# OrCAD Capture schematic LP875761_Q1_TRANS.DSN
size Custom; title: LP875761-Q1 4-Phase 16A Buck Converter with Integrated Switches; rev: 1.0; note: SNVSxxxx –SEPTEMBER 2020
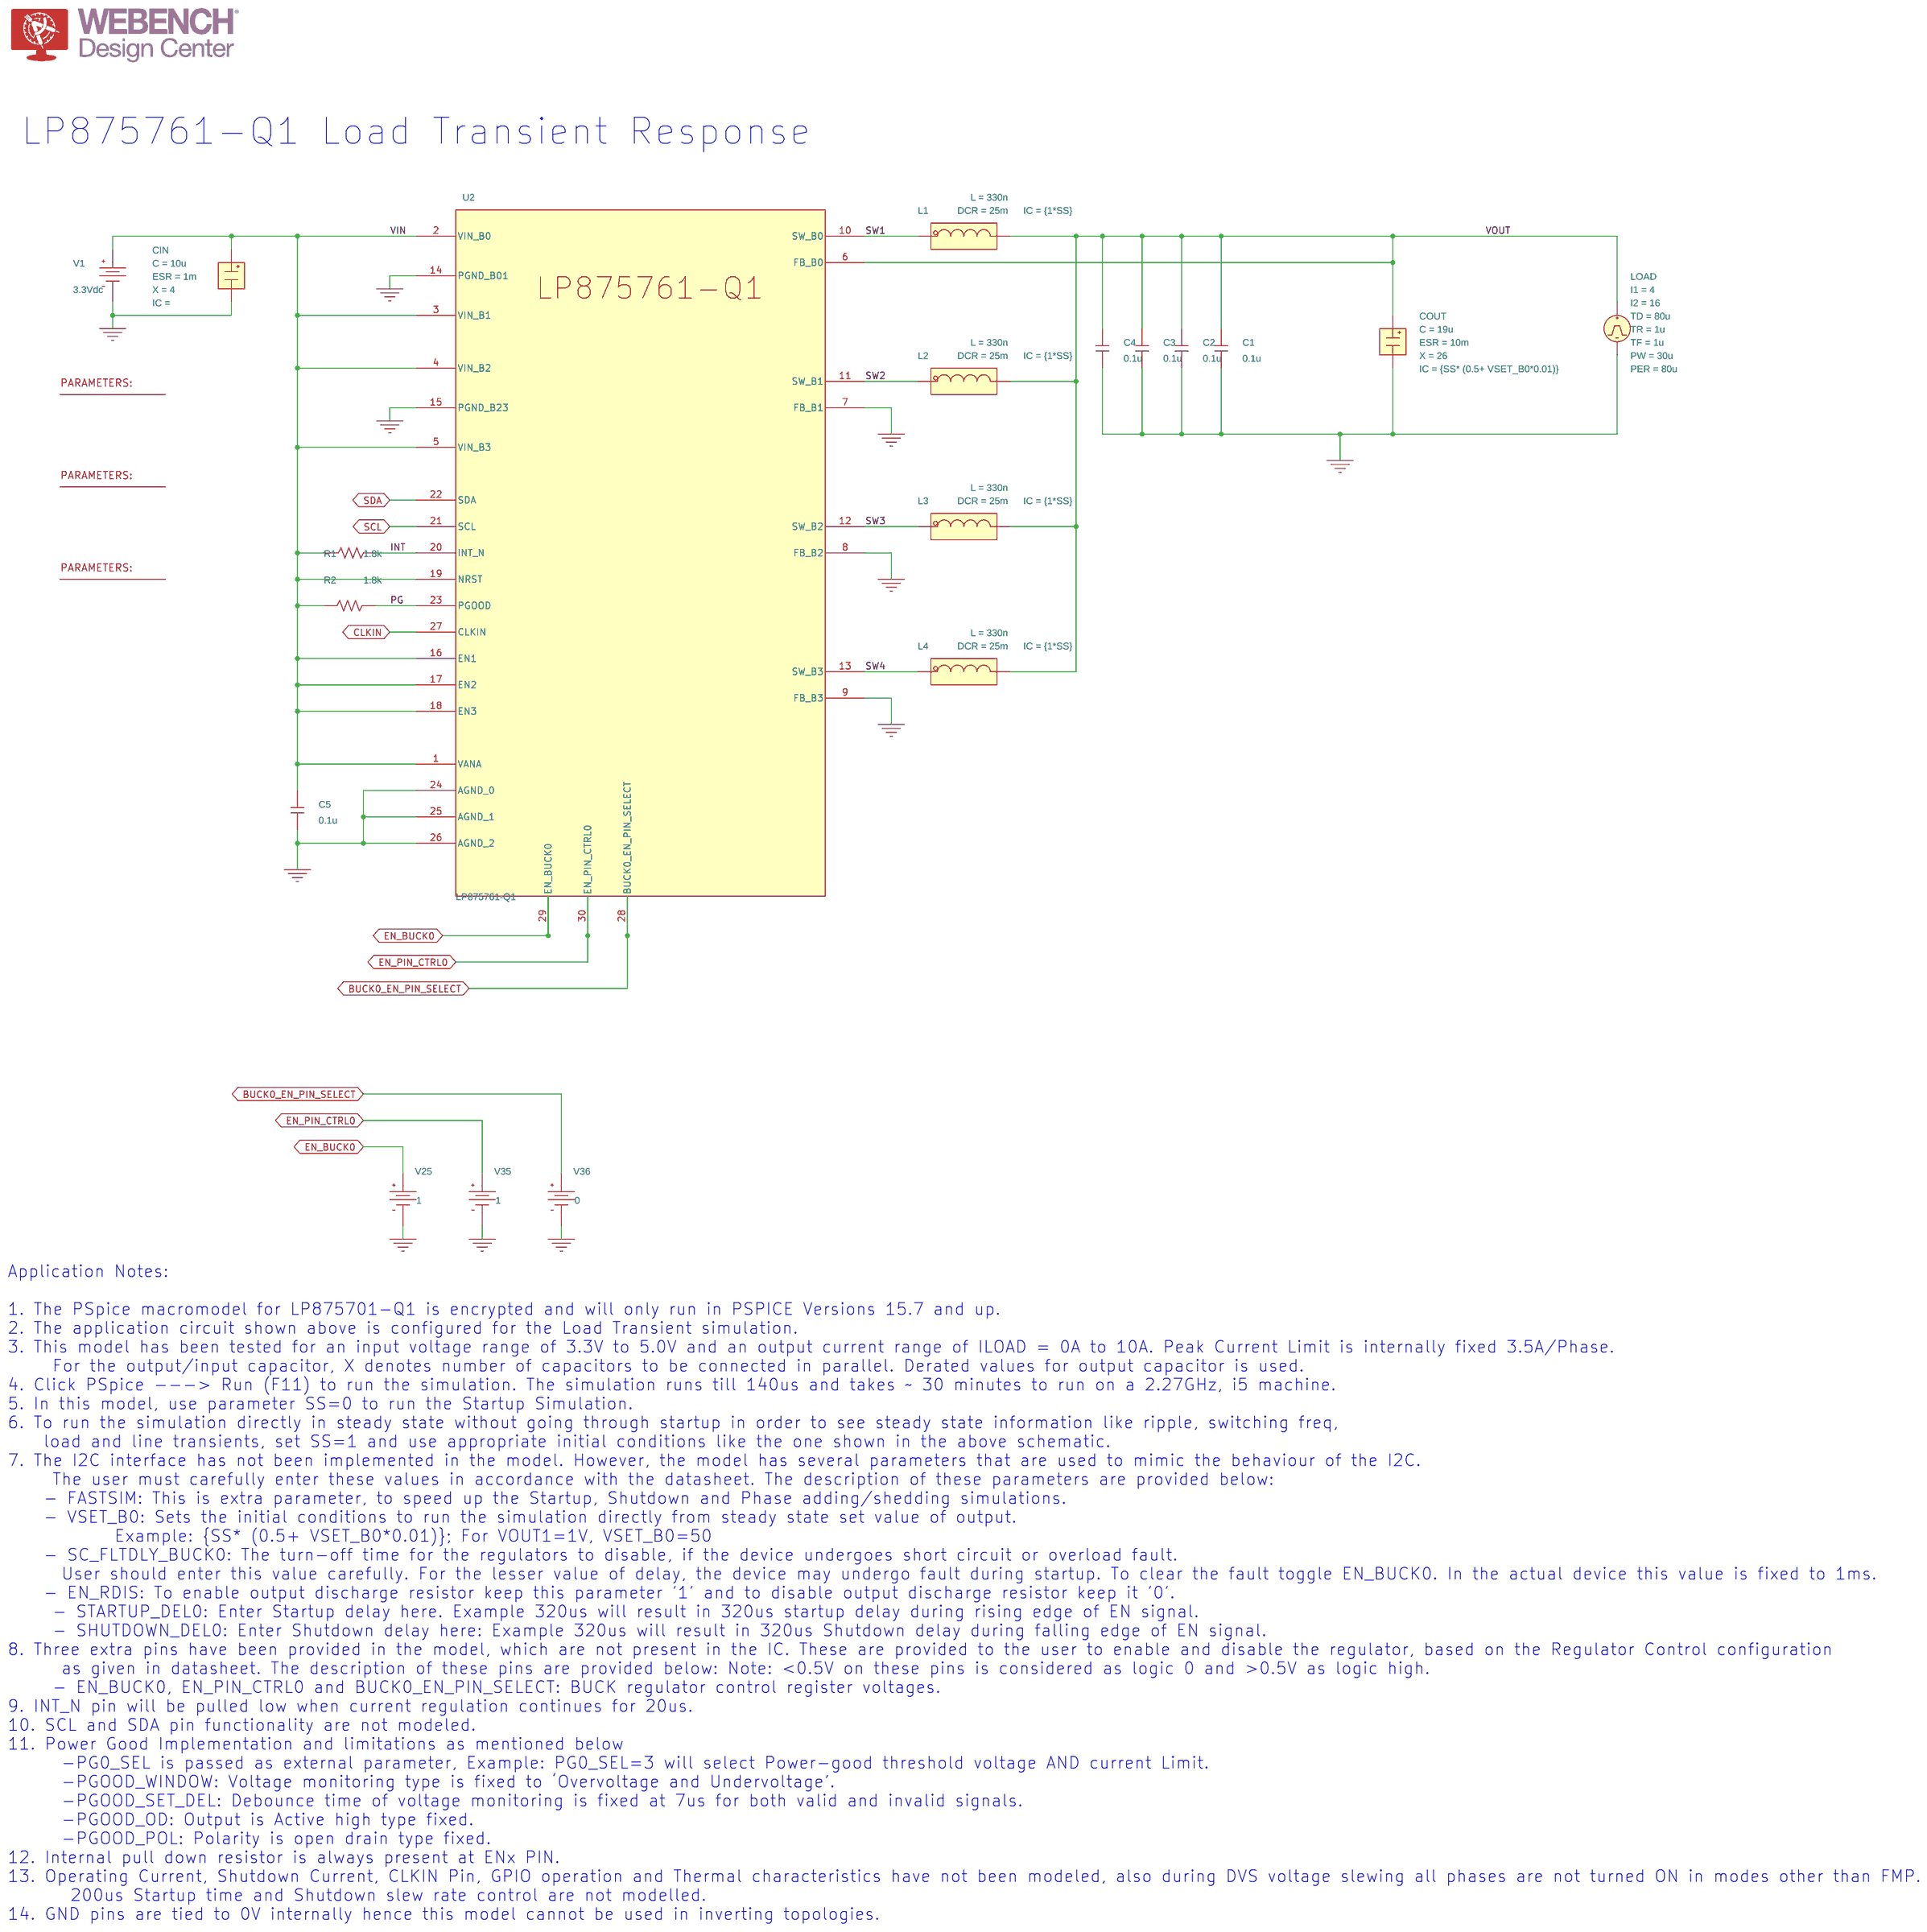
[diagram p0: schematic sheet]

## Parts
5  PARAM
7  PARAM
8  PARAM
C1  0.1u  [RAD/CK05]
C2  0.1u  [RAD/CK05]
C3  0.1u  [RAD/CK05]
C4  0.1u  [RAD/CK05]
C5  0.1u  [RAD/CK05]
CIN  CESR
COUT  CESR
L1  LDCR
L2  LDCR
L3  LDCR
L4  LDCR
LOAD  IPULSE
R1  1.8k  [AX/RC05]
R2  1.8k  [AX/RC05]
U2  LP875761-Q1
V1  VDC
V25  VDC
V35  VDC
V36  VDC

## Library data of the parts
5 = PARAM: EN_RDIS: 1; PG0_SEL: 3; SC_FLTDLY_BUCK0: 1m; SHUTDOWN_DEL0: 0; STARTUP_DEL0: 0
7 = PARAM: BUCK0_FPWM_MP: 1; BUCK0_PFM_FPWM: 1; FASTSIM: 1; SLEW_RATE0: 4
8 = PARAM: SS: 1; VSET_B0: 50
C1-C5 = C
CIN = CESR: C: 10u; ESR: 1m; PSpiceTemplate: X^@REFDES %IN %OUT @MODEL PARAMS:  ?C|C=@C||C=100u|  ?ESR|ESR=@ESR||ESR=0.01| ?X|X=@X||X=2|  ?IC|IC=@IC||IC=2|; X: 4
COUT = CESR: C: 19u; ESR: 10m; IC: {SS* (0.5+ VSET_B0*0.01)}; PSpiceTemplate: X^@REFDES %IN %OUT @MODEL PARAMS:  ?C|C=@C||C=100u|  ?ESR|ESR=@ESR||ESR=0.01| ?X|X=@X||X=2|  ?IC|IC=@IC||IC=2|; X: 26
L1-L4 = LDCR: DCR: 25m; IC: {1*SS}; L: 330n; PSpiceTemplate: X^@REFDES %IN %OUT @MODEL PARAMS:  ?L|L=@L||L=1u|  ?DCR|DCR=@DCR||DCR=0.01| ?IC|IC=@IC||IC=0|
LOAD = IPULSE: I1: 4; I2: 16; PER: 80u; PW: 30u; TD: 80u; TF: 1u; TR: 1u
R1 R2 = R
U2 = LP875761-Q1_TRANS_1
V1 = VDC: DC: 3.3Vdc
V25 V35 = VDC: DC: 1
V36 = VDC: DC: 0

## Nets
VIN: C5.2 CIN.1(IN) R1.1 R2.2 U2.1(VANA) U2.2(VIN_B0) U2.3(VIN_B1) U2.4(VIN_B2) U2.5(VIN_B3) U2.16(EN1) U2.17(EN2) U2.18(EN3) U2.19(NRST) V1.0(+)
0: C1.1 C2.1 C3.1 C4.1 C5.1 CIN.3(OUT) COUT.3(OUT) LOAD.2(-) U2.7(FB_B1) U2.8(FB_B2) U2.9(FB_B3) U2.14(PGND_B01) U2.15(PGND_B23) U2.24(AGND_0) U2.25(AGND_1) U2.26(AGND_2) V1.1(-) V25.1(-) V35.1(-) V36.1(-)
BUCK0_EN_PIN_SELECT: U2.28(BUCK0_EN_PIN_SELECT) V36.0(+)
CLKIN: U2.27(CLKIN)
EN_BUCK0: U2.29(EN_BUCK0) V25.0(+)
EN_PIN_CTRL0: U2.30(EN_PIN_CTRL0) V35.0(+)
INT: R1.2 U2.20(INT_N)
PG: R2.1 U2.23(PGOOD)
SCL: U2.21(SCL)
SDA: U2.22(SDA)
SW1: L1.1(IN) U2.10(SW_B0)
SW2: L2.1(IN) U2.11(SW_B1)
SW3: L3.1(IN) U2.12(SW_B2)
SW4: L4.1(IN) U2.13(SW_B3)
VOUT: C1.2 C2.2 C3.2 C4.2 COUT.1(IN) L1.3(OUT) L2.3(OUT) L3.3(OUT) L4.3(OUT) LOAD.1(+) U2.6(FB_B0)

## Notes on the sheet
- LP875761-Q1 Load Transient Response
- Application Notes:
  1. The PSpice macromodel for LP875701-Q1 is encrypted and will only run in PSPICE Versions 15.7 and up.
  2. The application circuit shown above is configured for the Load Transient simulation.
  3. This model has been tested for an input voltage range of 3.3V to 5.0V and an output current range of ILOAD = 0A to 10A. Peak Current Limit is internally fixed 3.5A/Phase.
       For the output/input capacitor, X denotes number of capacitors to be connected in parallel. Derated values for output capacitor is used.
  4. Click PSpice ---> Run (F11) to run the simulation. The simulation runs till 140us and takes ~ 30 minutes to run on a 2.27GHz, i5 machine.
  5. In this model, use parameter SS=0 to run the Startup Simulation.
  6. To run the simulation directly in steady state without going through startup in order to see steady state information like ripple, switching freq,
      load and line transients, set SS=1 and use appropriate initial conditions like the one shown in the above schematic.
  7. The I2C interface has not been implemented in the model. However, the model has several parameters that are used to mimic the behaviour of the I2C.
       The user must carefully enter these values in accordance with the datasheet. The description of these parameters are provided below:
      - FASTSIM: This is extra parameter, to speed up the Startup, Shutdown and Phase adding/shedding simulations.
      - VSET_B0: Sets the initial conditions to run the simulation directly from steady state set value of output.
  	       Example: {SS* (0.5+ VSET_B0*0.01)}; For VOUT1=1V, VSET_B0=50
      - SC_FLTDLY_BUCK0: The turn-off time for the regulators to disable, if the device undergoes short circuit or overload fault.
        User should enter this value carefully. For the lesser value of delay, the device may undergo fault during startup. To clear the fault toggle EN_BUCK0. In the actual device this value is fixed to 1ms.
      - EN_RDIS: To enable output discharge resistor keep this parameter '1' and to disable output discharge resistor keep it '0'.
       - STARTUP_DEL0: Enter Startup delay here. Example 320us will result in 320us startup delay during rising edge of EN signal.
       - SHUTDOWN_DEL0: Enter Shutdown delay here: Example 320us will result in 320us Shutdown delay during falling edge of EN signal.
  8. Three extra pins have been provided in the model, which are not present in the IC. These are provided to the user to enable and disable the regulator, based on the Regulator Control configuration
        as given in datasheet. The description of these pins are provided below: Note: <0.5V on these pins is considered as logic 0 and >0.5V as logic high.
       - EN_BUCK0, EN_PIN_CTRL0 and BUCK0_EN_PIN_SELECT: BUCK regulator control register voltages.
  9. INT_N pin will be pulled low when current regulation continues for 20us.
  10. SCL and SDA pin functionality are not modeled.
  11. Power Good Implementation and limitations as mentioned below
        -PG0_SEL is passed as external parameter, Example: PG0_SEL=3 will select Power-good threshold voltage AND current Limit.
        -PGOOD_WINDOW: Voltage monitoring type is fixed to ‘Overvoltage and Undervoltage’.
        -PGOOD_SET_DEL: Debounce time of voltage monitoring is fixed at 7us for both valid and invalid signals.
        -PGOOD_OD: Output is Active high type fixed.
        -PGOOD_POL: Polarity is open drain type fixed.
  12. Internal pull down resistor is always present at ENx PIN.
  13. Operating Current, Shutdown Current, CLKIN Pin, GPIO operation and Thermal characteristics have not been modeled, also during DVS voltage slewing all phases are not turned ON in modes other than FMP.
         200us Startup time and Shutdown slew rate control are not modelled.
  14. GND pins are tied to 0V internally hence this model cannot be used in inverting topologies.
